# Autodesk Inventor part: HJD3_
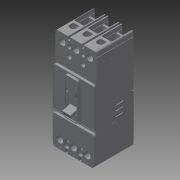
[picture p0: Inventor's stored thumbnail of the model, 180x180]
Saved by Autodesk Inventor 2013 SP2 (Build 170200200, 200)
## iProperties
Created: 2014-08
Part Number: HJD3_
Material: Generic
Document SubType Name: Modeling
Designer: EM/EM
Density: 1 g/cm^3
Description: TYPE HJD THERMAL MAGNETIC CIRCUIT BREAKERS THREE POLE, SERIES C
MXEDIT: false
MXINVTNRV: INV Versioned Component|HJD3_|004.0
Author: EM/EM
Revision Number: 004
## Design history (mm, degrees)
derived "JD3_.iam"
node "L1"
node "L2"
node "L3"
node "T1"
node "T2"
node "T3"
sketch "Sketch1"
  geometry: C1 r 10.795 at (11.494, 11.913) reference; C2 r 10.795 at (11.494, 11.913); 1 further point
  constraints: 1 centre point, 1 coincident
  dimensions: "d1" = 21.59 diameter of C2
extrude "Extrusion1" cut sketch "Sketch1" distance "d2" = 9.525; taper "d3" = 0 deg
sketch "Sketch2"
  geometry: C1 r 6.35 at (0, 0) reference; C2 r 6.35 at (0, 0); 1 further point
  constraints: 1 centre point, 1 coincident, 1 concentric
extrude "Extrusion2" cut sketch "Sketch2" distance "d4" = 9.525; taper "d6" = 0 deg; dims "d5" = 4.7752, "d7" = 0
sketch "Sketch3"
  geometry: C1 r 10.795 at (11.494, 11.913) reference; C2 r 10.795 at (11.494, 11.913); 1 further point
  constraints: 1 centre point, 1 coincident
  dimensions: "d8" = 21.59 diameter of C2
extrude "Extrusion3" cut sketch "Sketch3" distance "d9" = 9.525; taper "d10" = 0 deg
sketch "Sketch4"
  geometry: C1 r 6.35 at (0, 0) reference; C2 r 6.35 at (0, 0); 1 further point
  constraints: 1 centre point, 1 coincident, 1 concentric
extrude "Extrusion4" cut sketch "Sketch4" distance "d11" = 9.525; taper "d13" = 0 deg; dims "d12" = 4.7752, "d14" = 0
sketch "Sketch5"
  geometry: C1 r 10.795 at (8.89, 11.913) reference; C2 r 10.795 at (8.89, 11.913); 1 further point
  constraints: 1 centre point, 1 coincident
  dimensions: "d15" = 21.59 diameter of C2
extrude "Extrusion5" cut sketch "Sketch5" distance "d16" = 9.525; taper "d17" = 0 deg
sketch "Sketch6"
  geometry: C1 r 6.35 at (0, 0) reference; C2 r 6.35 at (0, 0); 1 further point
  constraints: 1 centre point, 1 coincident, 1 concentric
extrude "Extrusion6" cut sketch "Sketch6" distance "d18" = 9.525; taper "d20" = 0 deg; dims "d19" = 4.7752, "d21" = 0
sketch "Sketch7"
  geometry: C1 r 8.738 at (0.013, 0) reference; C2 r 8.738 at (0.013, 0); 1 further point
  constraints: 1 centre point, 1 coincident, 1 concentric
extrude "Extrusion7" cut sketch "Sketch7" distance "d22" = 9.525; taper "d23" = 0 deg; dims "d24" = 4.7752, "d25" = 0
sketch "Sketch8"
  geometry: C1 r 8.738 at (-0.013, 0) reference; C2 r 8.738 at (-0.013, 0); 1 further point
  constraints: 1 centre point, 1 coincident, 1 concentric
extrude "Extrusion8" cut sketch "Sketch8" distance "d26" = 9.525; taper "d28" = 0 deg; dims "d27" = 4.7752, "d29" = 0
sketch "Sketch9"
  geometry: C1 r 8.738 at (-0.038, 0) reference; C2 r 8.738 at (-0.038, 0); 1 further point
  constraints: 1 centre point, 1 coincident, 1 concentric
extrude "Extrusion9" cut sketch "Sketch9" distance "d30" = 9.525; taper "d32" = 0 deg; dims "d31" = 4.7752, "d33" = 0
body "Solid1"
node "JD3_.ipt:1"
